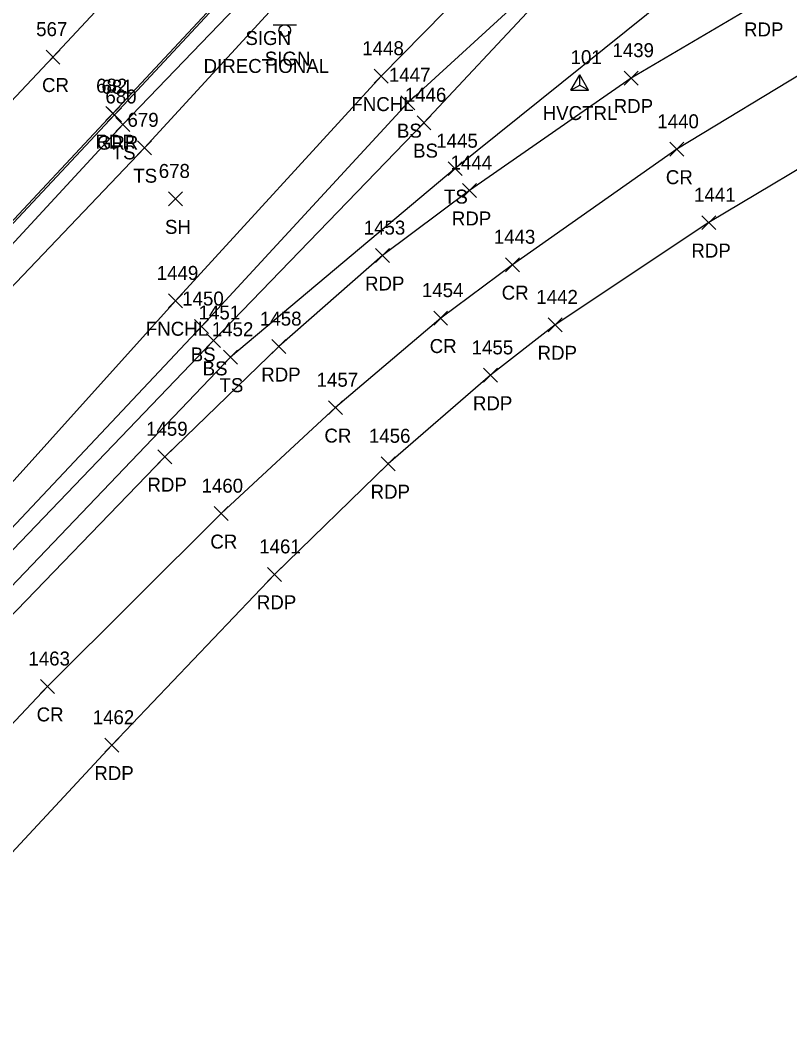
# Model space of a CAD drawing. Extents: x 1688195 to 1692013, y 424605 to 441234.
# Drawn here: x 1691514.7 to 1691624.9, y 438896.5 to 439041.4 of the extents above; entities that cross this region are included whole.
import ezdxf

# ---------------------------------------------------------------- set-up
doc = ezdxf.new("R2010")
doc.units = 0
for name, color, linetype in [('C_A', 7, 'Continuous'), ('C_I', 7, 'Continuous'), ('CPSM', 7, 'Continuous'), ('L_A', 7, 'Continuous'), ('L_I', 7, 'Continuous'), ('L_TIC', 7, 'Continuous'), ('LELB', 7, 'Continuous'), ('LFNC', 7, 'Continuous'), ('P_A', 7, 'Continuous'), ('P_I', 7, 'Continuous'), ('P_TIC', 7, 'Continuous'), ('PET', 7, 'Continuous'), ('PRC', 7, 'Continuous'), ('R_A', 7, 'Continuous'), ('R_I', 7, 'Continuous'), ('R_TIC', 7, 'Continuous'), ('RGR', 7, 'Continuous'), ('S_A', 7, 'Continuous'), ('S_C', 7, 'Continuous'), ('SSGN', 7, 'Continuous')]:
    doc.layers.add(name, color=color, linetype=linetype)

msp = doc.modelspace()

# ---------------------------------------------------------------- linework, layer by layer
at = {"layer": 'CPSM'}
for p, q in [((1691593.58, 439031.38), (1691594.83, 439033.55)), ((1691593.58, 439031.38), (1691594.83, 439033.55)), ((1691596.08, 439031.38), (1691594.83, 439033.55)), ((1691594.83, 439032.1), (1691594.83, 439033.55)), ((1691596.08, 439031.38), (1691594.83, 439033.55)), ((1691594.83, 439032.1), (1691594.83, 439033.55)), ((1691593.58, 439031.38), (1691594.83, 439032.1)), ((1691593.58, 439031.38), (1691594.83, 439032.1)), ((1691594.83, 439032.1), (1691594.83, 439032.1)), ((1691594.83, 439032.1), (1691596.08, 439031.38)), ((1691594.83, 439032.1), (1691594.83, 439032.1)), ((1691594.83, 439032.1), (1691596.08, 439031.38)), ((1691593.58, 439031.38), (1691596.08, 439031.38)), ((1691593.58, 439031.38), (1691596.08, 439031.38))]:
    msp.add_line(p, q, dxfattribs=at)
at = {"layer": 'L_TIC'}
for points in [[(1691565.38, 439032.38), (1691567.38, 439034.38)], [(1691567.38, 439032.38), (1691565.38, 439034.38)], [(1691569.2, 439028.58), (1691571.2, 439030.58)], [(1691571.2, 439028.58), (1691569.2, 439030.58)], [(1691528.39, 439025.47), (1691530.39, 439027.47)], [(1691530.39, 439025.47), (1691528.39, 439027.47)], [(1691571.53, 439025.72), (1691573.53, 439027.72)], [(1691573.53, 439025.72), (1691571.53, 439027.72)], [(1691531.48, 439022.13), (1691533.48, 439024.13)], [(1691533.48, 439022.13), (1691531.48, 439024.13)], [(1691575.98, 439019.14), (1691577.98, 439021.14)], [(1691577.98, 439019.14), (1691575.98, 439021.14)], [(1691535.95, 439014.81), (1691537.95, 439016.81)], [(1691537.95, 439014.81), (1691535.95, 439016.81)], [(1691535.95, 439000.22), (1691537.95, 439002.22)], [(1691537.95, 439000.22), (1691535.95, 439002.22)], [(1691539.68, 438996.55), (1691541.68, 438998.55)], [(1691541.68, 438996.55), (1691539.68, 438998.55)], [(1691541.38, 438994.55), (1691543.38, 438996.55)], [(1691543.38, 438994.55), (1691541.38, 438996.55)], [(1691543.83, 438992.15), (1691545.83, 438994.15)], [(1691545.83, 438992.15), (1691543.83, 438994.15)]]:
    msp.add_lwpolyline(points, dxfattribs=at)
at = {"layer": 'LELB'}
for points in [[(1691809.05, 439198.7), (1691810.07, 439220.42), (1691810.47, 439227.71), (1691810.04, 439233.75), (1691820.98, 439231.16), (1691837.25, 439226.41), (1691844.55, 439222.68), (1691860.67, 439213.28), (1691879.41, 439197.19), (1691884.86, 439187.77), (1691888.44, 439178.13), (1691882, 439154.55), (1691849.25, 439142.61), (1691815.33, 439128.47), (1691761.5, 439106.68), (1691722.87, 439092.03), (1691697.52, 439087.73), (1691657.95, 439070.39), (1691613.62, 439049.58), (1691576.98, 439020.14), (1691544.83, 438993.15), (1691508.2, 438954.88), (1691488.69, 438935.2)], [(1691494.97, 438989.23), (1691529.39, 439026.47), (1691563.11, 439061.46), (1691592.32, 439093.25), (1691622.45, 439123.57), (1691640.28, 439144.55), (1691642.63, 439146.18), (1691644.54, 439148.64), (1691657.14, 439160.25), (1691677.5, 439185.53), (1691687.79, 439198.06), (1691700.53, 439206.6), (1691711.71, 439214.4), (1691729.93, 439221), (1691765.22, 439228.65), (1691785.8, 439230.06)], [(1691867.08, 439165.21), (1691844.95, 439160.27), (1691798.84, 439152.11), (1691745.51, 439147.11), (1691728.71, 439142.4), (1691709.09, 439133.88), (1691683, 439117.2), (1691643.28, 439091.08), (1691604.89, 439061.29), (1691572.53, 439026.72), (1691542.38, 438995.55), (1691505.84, 438957.5), (1691487.66, 438936.34), (1691466.81, 438915.54), (1691436.02, 438880.86), (1691415.55, 438858.76)], [(1691497.62, 438986.55), (1691532.48, 439023.13), (1691565.52, 439059.1), (1691594.4, 439089.96), (1691624.94, 439121.84), (1691642.24, 439143.61)], [(1691604.89, 439061.29), (1691570.2, 439029.58), (1691540.68, 438997.55), (1691504.19, 438958.83), (1691485.94, 438937.8), (1691466.29, 438916.24), (1691434.59, 438882.45), (1691414.01, 438860.1)]]:
    msp.add_lwpolyline(points, dxfattribs=at)
at = {"layer": 'LFNC'}
msp.add_lwpolyline([(1691844.63, 439219.19), (1691827.3, 439208.18), (1691808.98, 439197.07), (1691805.18, 439194.78), (1691802.65, 439193.15), (1691780.93, 439179.95), (1691740.49, 439155.55), (1691707.63, 439134.9), (1691682.09, 439120.04), (1691638.96, 439093.47), (1691599.84, 439067.34), (1691566.38, 439033.38), (1691536.95, 439001.22), (1691500.89, 438961.26), (1691462.91, 438919.55), (1691429.39, 438883.14), (1691411.26, 438863.12)], dxfattribs=at)
at = {"layer": 'P_TIC'}
for points in [[(1691518.39, 439035.11), (1691520.39, 439037.11)], [(1691520.39, 439035.11), (1691518.39, 439037.11)], [(1691601.22, 439032.1), (1691603.22, 439034.1)], [(1691603.22, 439032.1), (1691601.22, 439034.1)], [(1691526.98, 439027.02), (1691528.98, 439029.02)], [(1691528.98, 439027.02), (1691526.98, 439029.02)], [(1691607.73, 439021.92), (1691609.73, 439023.92)], [(1691609.73, 439021.92), (1691607.73, 439023.92)], [(1691578.03, 439016.01), (1691580.03, 439018.01)], [(1691580.03, 439016.01), (1691578.03, 439018.01)], [(1691612.34, 439011.41), (1691614.34, 439013.41)], [(1691614.34, 439011.41), (1691612.34, 439013.41)], [(1691565.59, 439006.7), (1691567.59, 439008.7)], [(1691567.59, 439006.7), (1691565.59, 439008.7)], [(1691584.22, 439005.39), (1691586.22, 439007.39)], [(1691586.22, 439005.39), (1691584.22, 439007.39)], [(1691573.92, 438997.75), (1691575.92, 438999.75)], [(1691575.92, 438997.75), (1691573.92, 438999.75)], [(1691590.31, 438996.78), (1691592.31, 438998.78)], [(1691592.31, 438996.78), (1691590.31, 438998.78)], [(1691550.73, 438993.67), (1691552.73, 438995.67)], [(1691552.73, 438993.67), (1691550.73, 438995.67)], [(1691581.05, 438989.56), (1691583.05, 438991.56)], [(1691583.05, 438989.56), (1691581.05, 438991.56)], [(1691558.84, 438984.93), (1691560.84, 438986.93)], [(1691560.84, 438984.93), (1691558.84, 438986.93)], [(1691534.43, 438977.91), (1691536.43, 438979.91)], [(1691536.43, 438977.91), (1691534.43, 438979.91)], [(1691566.39, 438976.9), (1691568.39, 438978.9)], [(1691568.39, 438976.9), (1691566.39, 438978.9)], [(1691542.5, 438969.76), (1691544.5, 438971.76)], [(1691544.5, 438969.76), (1691542.5, 438971.76)], [(1691550.1, 438961.07), (1691552.1, 438963.07)], [(1691552.1, 438961.07), (1691550.1, 438963.07)], [(1691517.61, 438945.02), (1691519.61, 438947.02)], [(1691519.61, 438945.02), (1691517.61, 438947.02)], [(1691526.82, 438936.62), (1691528.82, 438938.62)], [(1691528.82, 438936.62), (1691526.82, 438938.62)]]:
    msp.add_lwpolyline(points, dxfattribs=at)
at = {"layer": 'PET'}
for points in [[(1691392.15, 438883.12), (1691415.43, 438907.79), (1691443.51, 438937.17), (1691473.2, 438969.34), (1691494.19, 438991.98), (1691527.98, 439028.02), (1691561.01, 439063.43)], [(1691620.88, 439044.07), (1691602.22, 439033.1), (1691579.03, 439017.01), (1691566.59, 439007.7), (1691551.73, 438994.67), (1691535.43, 438978.91), (1691510.19, 438952.85), (1691471.21, 438911.57), (1691440.28, 438877.12), (1691419.08, 438855.12)], [(1691672.86, 439042.9), (1691649.54, 439032.89), (1691634.02, 439024.76), (1691613.34, 439012.41), (1691591.31, 438997.78), (1691582.05, 438990.56), (1691567.39, 438977.9), (1691551.1, 438962.07), (1691527.82, 438937.62), (1691487.26, 438894.03), (1691457.21, 438860.6), (1691436.01, 438838.17)]]:
    msp.add_lwpolyline(points, dxfattribs=at)
at = {"layer": 'PRC'}
for points in [[(1691383.45, 438891.46), (1691410.11, 438918.45), (1691432.71, 438943.44), (1691460.69, 438973.59), (1691487.77, 439002.58), (1691519.39, 439036.11), (1691551.83, 439070.88), (1691579.21, 439100.29), (1691605.82, 439129.37), (1691637.88, 439164.38), (1691665.6, 439193.96), (1691687.96, 439216.92), (1691714.01, 439245.27), (1691730.35, 439261.96), (1691750.53, 439284.62), (1691763.38, 439297.71)], [(1691888.13, 439193.66), (1691921.53, 439164.99), (1691933.61, 439155.1), (1691905.33, 439143.8), (1691864.7, 439127.18), (1691822.78, 439112.3), (1691787.26, 439099.58), (1691756.92, 439088.3), (1691729.19, 439077.85), (1691704.03, 439068.3), (1691667.7, 439053.5), (1691645.71, 439043.49), (1691628.46, 439034.88), (1691608.73, 439022.92), (1691585.22, 439006.39), (1691574.92, 438998.75), (1691559.84, 438985.93), (1691543.5, 438970.76), (1691518.61, 438946.02), (1691478.27, 438903.21), (1691447.81, 438870), (1691426.94, 438847.45)]]:
    msp.add_lwpolyline(points, dxfattribs=at)
at = {"layer": 'R_TIC'}
for points in [[(1691527.19, 439026.86), (1691529.19, 439028.86)], [(1691529.19, 439026.86), (1691527.19, 439028.86)]]:
    msp.add_lwpolyline(points, dxfattribs=at)
at = {"layer": 'RGR'}
msp.add_lwpolyline([(1691392.43, 438882.91), (1691415.63, 438907.66), (1691443.42, 438937.01), (1691473.56, 438969.15), (1691494.4, 438991.79), (1691528.19, 439027.86), (1691561.17, 439063.3), (1691590.77, 439094.95), (1691620.16, 439126.42), (1691638.64, 439146.14), (1691654.09, 439162.7)], dxfattribs=at)
at = {"layer": 'SSGN'}
for p, q in [((1691550.94, 439040.74), (1691554.27, 439040.74)), ((1691552.59, 439039.91), (1691552.59, 439039.91))]:
    msp.add_line(p, q, dxfattribs=at)
msp.add_circle((1691552.59, 439039.91), 0.833, dxfattribs=at)

# ---------------------------------------------------------------- texts
at = {"layer": 'C_A'}
msp.add_text('HVCTRL', height=2, dxfattribs=at).set_placement((1691589.53, 439027.1))
msp.add_text('HVCTRL', height=2, dxfattribs=at).set_placement((1691589.53, 439027.1))
at = {"layer": 'C_I'}
msp.add_text('101', height=2, dxfattribs=at).set_placement((1691593.53, 439035.1))
msp.add_text('101', height=2, dxfattribs=at).set_placement((1691593.53, 439035.1))
at = {"layer": 'L_A'}
for s, p in [('FNCHL', (1691562.13, 439028.38)), ('BS', (1691568.65, 439024.58)), ('TS', (1691527.8, 439021.47)), ('BS', (1691570.97, 439021.72)), ('TS', (1691530.89, 439018.13)), ('TS', (1691575.39, 439015.14)), ('SH', (1691535.43, 439010.81)), ('FNCHL', (1691532.69, 438996.22)), ('BS', (1691539.12, 438992.55)), ('BS', (1691540.82, 438990.55)), ('TS', (1691543.24, 438988.15))]:
    msp.add_text(s, height=2, dxfattribs=at).set_placement(p)
at = {"layer": 'L_I'}
for s, p in [('1448', (1691563.69, 439036.38)), ('1447', (1691567.51, 439032.58)), ('1446', (1691569.78, 439029.72)), ('680', (1691526.9, 439029.47)), ('679', (1691530.06, 439026.13)), ('1445', (1691574.29, 439023.14)), ('678', (1691534.54, 439018.81)), ('1449', (1691534.25, 439004.22)), ('1450', (1691537.9, 439000.55)), ('1451', (1691540.25, 438998.55)), ('1452', (1691542.14, 438996.15))]:
    msp.add_text(s, height=2, dxfattribs=at).set_placement(p)
at = {"layer": 'P_A'}
for s, p in [('RDP', (1691618.37, 439039.07)), ('CR', (1691517.82, 439031.11)), ('RDP', (1691599.7, 439028.1)), ('RDP', (1691525.46, 439023.02)), ('CR', (1691607.17, 439017.92)), ('RDP', (1691576.52, 439012.01)), ('RDP', (1691610.83, 439007.41)), ('RDP', (1691564.08, 439002.7)), ('CR', (1691583.66, 439001.39)), ('CR', (1691573.35, 438993.75)), ('RDP', (1691588.8, 438992.78)), ('RDP', (1691549.22, 438989.67)), ('RDP', (1691579.54, 438985.56)), ('CR', (1691558.27, 438980.93)), ('RDP', (1691532.92, 438973.91)), ('RDP', (1691564.88, 438972.9)), ('CR', (1691541.93, 438965.76)), ('RDP', (1691548.59, 438957.07)), ('CR', (1691517.05, 438941.02)), ('RDP', (1691525.31, 438932.62))]:
    msp.add_text(s, height=2, dxfattribs=at).set_placement(p)
at = {"layer": 'P_I'}
for s, p in [('567', (1691516.98, 439039.11)), ('1439', (1691599.52, 439036.1)), ('682', (1691525.57, 439031.02)), ('1440', (1691605.95, 439025.92)), ('1444', (1691576.34, 439020.01)), ('1441', (1691611.21, 439015.41)), ('1453', (1691563.9, 439010.7)), ('1443', (1691582.53, 439009.39)), ('1454', (1691572.23, 439001.75)), ('1442', (1691588.62, 439000.78)), ('1458', (1691549.04, 438997.67)), ('1455', (1691579.36, 438993.56)), ('1457', (1691557.15, 438988.93)), ('1459', (1691532.73, 438981.91)), ('1456', (1691564.64, 438980.9)), ('1460', (1691540.67, 438973.76)), ('1461', (1691548.93, 438965.07)), ('1463', (1691515.87, 438949.02)), ('1462', (1691525.08, 438940.62))]:
    msp.add_text(s, height=2, dxfattribs=at).set_placement(p)
at = {"layer": 'R_A'}
msp.add_text('GRR', height=2, dxfattribs=at).set_placement((1691525.67, 439022.86))
at = {"layer": 'R_I'}
msp.add_text('681', height=2, dxfattribs=at).set_placement((1691526.34, 439030.86))
at = {"layer": 'S_A'}
for p in [(1691546.95, 439037.84), (1691549.73, 439034.89)]:
    msp.add_text('SIGN', height=2, dxfattribs=at).set_placement(p)
at = {"layer": 'S_C'}
msp.add_text('DIRECTIONAL', height=2, dxfattribs=at).set_placement((1691540.96, 439033.84))

doc.saveas('drawing.dxf')
